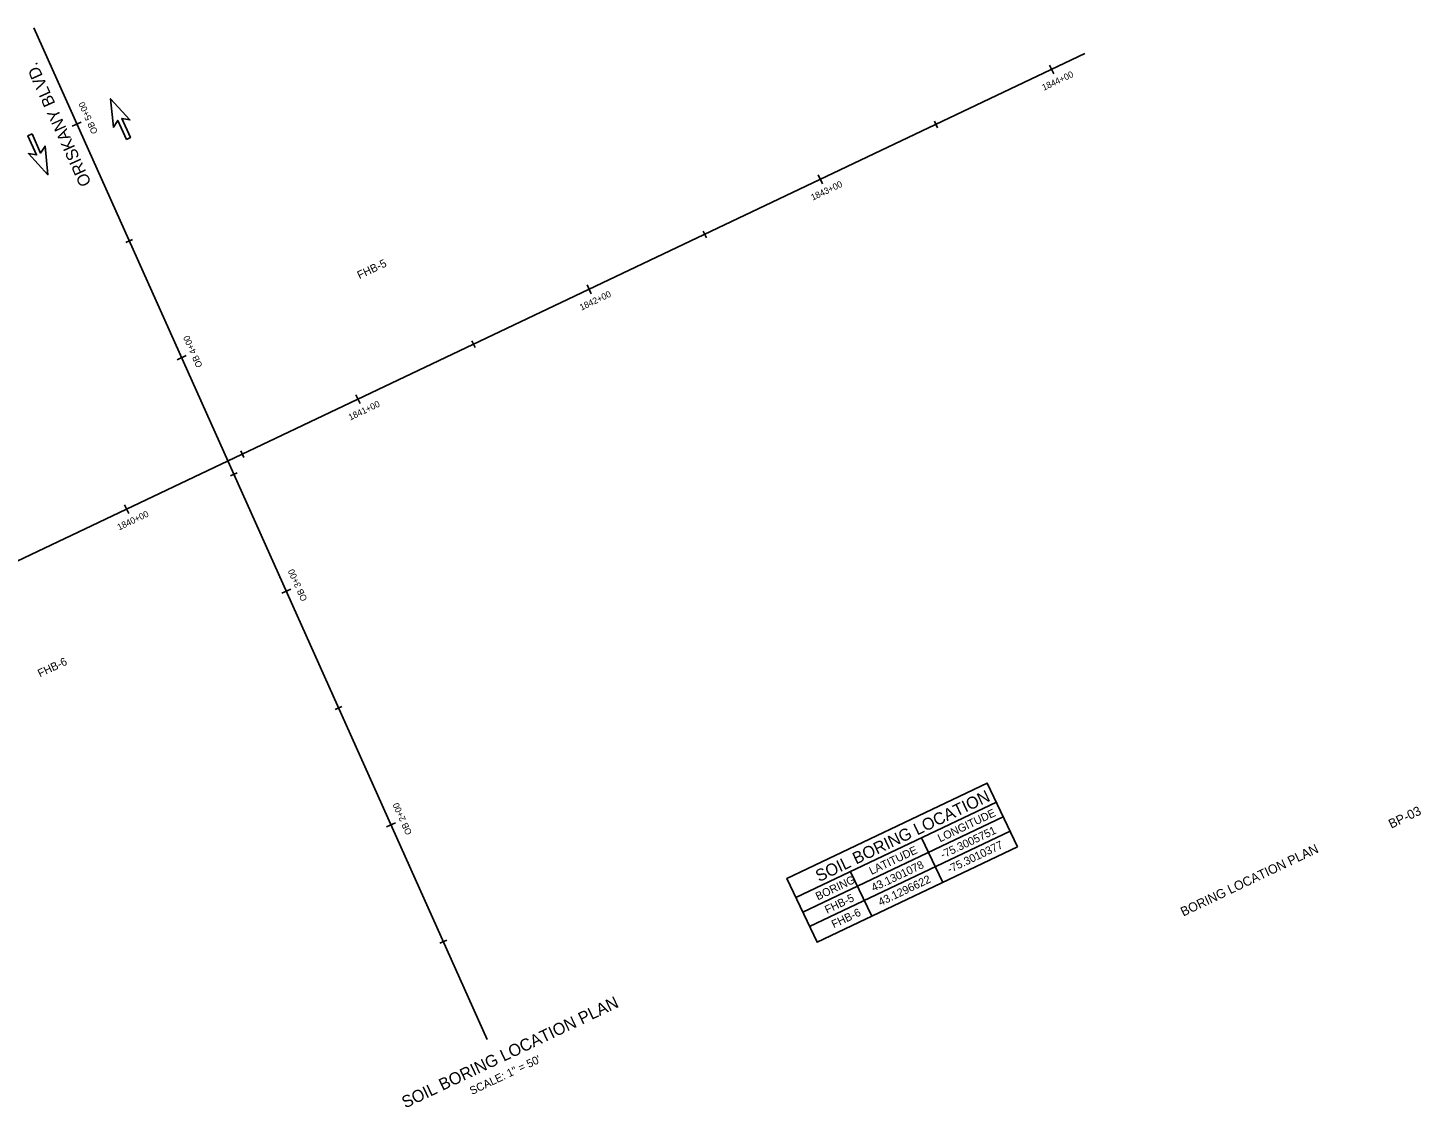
# Model space of a CAD drawing. Extents: x 1162151 to 1163042, y 1142576 to 1143214.
# Drawn here: x 1162498 to 1163042, y 1142783 to 1143205 of the extents above; entities that cross this region are included whole.
import ezdxf

# ---------------------------------------------------------------- set-up
doc = ezdxf.new("R2010")
doc.units = 0
for name, color, linetype in [('GSCOLORFILL', 7, 'Continuous'), ('NDEFAULT_P_T', 7, 'Continuous'), ('O_Details_Dimensions_Extension_Lines_P', 7, 'Continuous'), ('O_Details_Text Normal Proposed_P_T', 7, 'Continuous'), ('SHEET_BORDER', 7, 'Continuous'), ('SHEET_BORDER_TEXT_SHEETINFO', 7, 'Continuous'), ('SHEET_CLIPPING', 7, 'Continuous')]:
    doc.layers.add(name, color=color, linetype=linetype)

msp = doc.modelspace()

# ---------------------------------------------------------------- linework, layer by layer
at = {"layer": 'GSCOLORFILL'}
for p, q in [((1162677.56, 1142810.12), (1162500.4, 1143205.23)), ((1162213.43, 1142863.58), (1162911.07, 1143195.18))]:
    msp.add_line(p, q, dxfattribs=at)
at = {"layer": 'O_Details_Dimensions_Extension_Lines_P'}
for points in [[(1162897.21, 1143190.71), (1162898.86, 1143187.25)], [(1162515.49, 1143166.88), (1162518.99, 1143168.45)], [(1162852.26, 1143168.82), (1162853.49, 1143166.21)], [(1162806.89, 1143147.79), (1162808.54, 1143144.32)], [(1162536.38, 1143121.45), (1162539.01, 1143122.63)], [(1162761.94, 1143125.89), (1162763.18, 1143123.29)], [(1162716.57, 1143104.86), (1162718.22, 1143101.39)], [(1162671.62, 1143082.96), (1162672.86, 1143080.36)], [(1162556.4, 1143075.63), (1162559.91, 1143077.21)], [(1162626.26, 1143061.93), (1162627.91, 1143058.46)], [(1162581.31, 1143040.03), (1162582.54, 1143037.43)], [(1162577.3, 1143030.21), (1162579.93, 1143031.39)], [(1162535.94, 1143019), (1162537.59, 1143015.53)], [(1162597.32, 1142984.39), (1162600.82, 1142985.96)], [(1162618.21, 1142938.96), (1162620.84, 1142940.14)], [(1162638.23, 1142893.14), (1162641.73, 1142894.71)], [(1162659.12, 1142847.71), (1162661.75, 1142848.89)]]:
    msp.add_lwpolyline(points, dxfattribs=at)
at = {"layer": 'SHEET_BORDER_TEXT_SHEETINFO'}
for p, q in [((1162798.19, 1142865.54), (1162876.49, 1142902.76)), ((1162800.86, 1142859.91), (1162879.16, 1142897.13))]:
    msp.add_line(p, q, dxfattribs=at)
for points in [[(1162536.61, 1143161.63), (1162533.25, 1143169.11), (1162531.55, 1143166.41), (1162530.43, 1143177.56), (1162538.02, 1143169.31), (1162534.87, 1143169.84), (1162538.22, 1143162.35)], [(1162499.77, 1143163.81), (1162503.12, 1143156.32), (1162504.82, 1143159.03), (1162505.94, 1143147.88), (1162498.36, 1143156.13), (1162501.51, 1143155.6), (1162498.15, 1143163.08)], [(1162884.77, 1142885.34), (1162806.46, 1142848.12), (1162794.62, 1142873.04), (1162872.92, 1142910.26)]]:
    msp.add_lwpolyline(points, close=True, dxfattribs=at)
at = {"layer": 'SHEET_CLIPPING'}
for p, q in [((1162803.53, 1142854.29), (1162881.83, 1142891.51)), ((1162847.25, 1142888.86), (1162855.53, 1142871.45)), ((1162819.49, 1142875.67), (1162827.77, 1142858.25))]:
    msp.add_line(p, q, dxfattribs=at)

# ---------------------------------------------------------------- texts
at = {"layer": 'DEFPOINTS'}
for s, rotation, p in [('FHB-5', 25.4222, (1162627.68, 1143107.04)), ('FHB-6', 25.4222, (1162502.88, 1142951.5)), ('LONGITUDE', 25.4222, (1162854.48, 1142887.1)), ('-75.3005751', 25.4222, (1162855.55, 1142880.68)), ('LATITUDE', 25.4222, (1162827.69, 1142874.36)), ('-75.3010377', 25.4222, (1162858.17, 1142875)), ('43.1301078', 25.4222, (1162828.52, 1142867.83)), ('BORING', 25.4222, (1162806.75, 1142864.41)), ('43.1296622', 25.4222, (1162831.21, 1142862.19)), ('FHB-5', 25.4222, (1162810.34, 1142859.19)), ('FHB-6', 25.4222, (1162812.97, 1142853.52)), ('SCALE: 1" = 50\'', 25.36, (1162671.62, 1142788.44))]:
    msp.add_text(s, height=3.126, rotation=rotation, dxfattribs=at).set_placement(p)
at = {"layer": 'NDEFAULT_P_T'}
for s, p in [('BP-03', (1163030.73, 1142892.44)), ('BORING LOCATION PLAN', (1162949.5, 1142858.11))]:
    msp.add_text(s, height=3.6, rotation=25.4222, dxfattribs=at).set_placement(p)
at = {"layer": 'O_Details_Text Normal Proposed_P_T'}
for s, rotation, p in [('1844+00', 25.4222, (1162895.03, 1143180.63)), ('OB 5+00', 114.15, (1162525.51, 1143164.49)), ('1843+00', 25.4222, (1162804.75, 1143137.72)), ('1842+00', 25.4222, (1162714.39, 1143094.78)), ('OB 4+00', 114.15, (1162566.43, 1143073.24)), ('1841+00', 25.4222, (1162624.08, 1143051.85)), ('1840+00', 25.4222, (1162533.76, 1143008.92)), ('OB 3+00', 114.15, (1162607.33, 1142982.02)), ('OB 2+00', 114.15, (1162648.25, 1142890.74))]:
    msp.add_text(s, height=2.501, rotation=rotation, dxfattribs=at).set_placement(p)
at = {"layer": 'SHEET_BORDER'}
for s, height, rotation, p in [('ORISKANY BLVD.', 4.692, 114.3021, (1162523.01, 1143144.55)), ('SOIL BORING LOCATION', 4.68, 25.4222, (1162807.22, 1142871.56)), ('SOIL BORING LOCATION PLAN', 4.692, 25.4273, (1162645.58, 1142783.15))]:
    msp.add_text(s, height=height, rotation=rotation, dxfattribs=at).set_placement(p)

doc.saveas('drawing.dxf')
